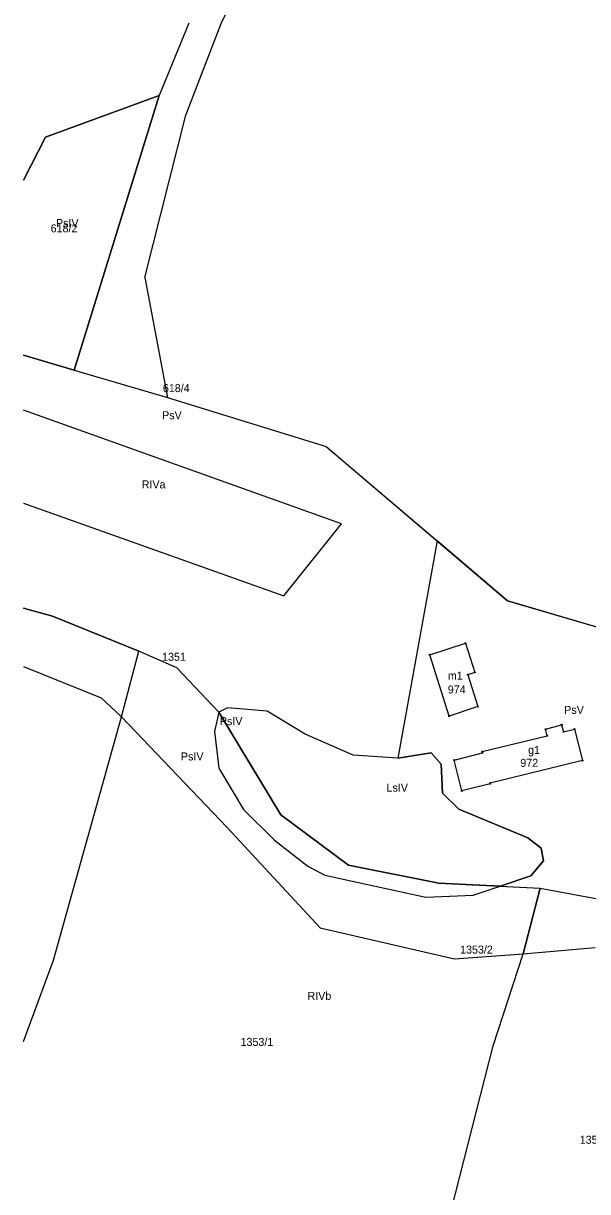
# Model space of a CAD drawing. Extents: x 7498273 to 7499989, y 5499795 to 5500810.
# Drawn here: x 7498273.2 to 7498378.9, y 5500193.5 to 5500412.5 of the extents above; entities that cross this region are included whole.
import ezdxf

# ---------------------------------------------------------------- set-up
doc = ezdxf.new("R2010")
doc.units = 0
for name, color, linetype in [('209-oznaczenie konturu klasyfikacyjnego', 7, 'Continuous'), ('211-numer działki ewidencyjnej', 7, 'Continuous'), ('217-kontur klasyfikacyjny', 7, 'Continuous'), ('218-kontur użytku gruntowego', 7, 'Continuous'), ('219-działka ewidencyjna', 7, 'Continuous'), ('312-budynek ewidencyjny', 7, 'Continuous'), ('312-oznaczenie budynku ewidencyjnego', 7, 'Continuous'), ('312-oznaczenie budynku ewidencyjnego-Atr117', 7, 'Continuous'), ('Punkt budynku', 7, 'Continuous')]:
    doc.layers.add(name, color=color, linetype=linetype)

# ---------------------------------------------------------------- blocks, each defined once
blk = doc.blocks.new('PUNKTBUD')
blk.add_circle((0, 0), 0.09)

msp = doc.modelspace()

# ---------------------------------------------------------------- linework, layer by layer
at = {"layer": '217-kontur klasyfikacyjny'}
for points in [[(7498304.21, 5500412.52), (7498298.63, 5500398.96)], [(7498298.63, 5500398.96), (7498277.31, 5500391.13)], [(7498298.63, 5500398.96), (7498282.7, 5500347.49)], [(7498277.31, 5500391.13), (7498273.174, 5500383.069)], [(7498282.7, 5500347.49), (7498273.174, 5500350.256)], [(7498282.7, 5500347.49), (7498300.17, 5500342.36)], [(7498300.17, 5500342.36), (7498329.95, 5500333.19)], [(7498332.78, 5500318.69), (7498273.174, 5500339.962)], [(7498329.95, 5500333.19), (7498350.74, 5500315.46)], [(7498273.174, 5500322.559), (7498322, 5500305.16)], [(7498322, 5500305.16), (7498332.78, 5500318.69)], [(7498350.74, 5500315.46), (7498343.36, 5500274.78)], [(7498363.93, 5500304.21), (7498350.74, 5500315.46)], [(7498381.55, 5500299.07), (7498363.93, 5500304.21)], [(7498278.63, 5500301.34), (7498273.174, 5500302.837)], [(7498294.84, 5500294.79), (7498278.63, 5500301.34)], [(7498301.93, 5500291.67), (7498294.84, 5500294.79)], [(7498273.174, 5500291.909), (7498287.76, 5500286.06)], [(7498309.84, 5500283.36), (7498301.93, 5500291.67)], [(7498287.76, 5500286.06), (7498291.54, 5500282.5)], [(7498311.42, 5500284.16), (7498309.84, 5500283.36)], [(7498318.87, 5500283.54), (7498311.42, 5500284.16)], [(7498325.97, 5500279.26), (7498318.87, 5500283.54)], [(7498291.54, 5500282.5), (7498311.35, 5500261.75)], [(7498309.84, 5500283.36), (7498309, 5500279.74)], [(7498321.44, 5500264.13), (7498309.84, 5500283.36)], [(7498309, 5500279.74), (7498309.83, 5500272.91)], [(7498335.01, 5500275.33), (7498325.97, 5500279.26)], [(7498343.36, 5500274.78), (7498335.01, 5500275.33)], [(7498349.61, 5500275.76), (7498343.36, 5500274.78)], [(7498351.51, 5500273.61), (7498349.61, 5500275.76)], [(7498309.83, 5500272.91), (7498314.45, 5500265.12)], [(7498351.73, 5500268.22), (7498351.51, 5500273.61)], [(7498354.79, 5500265.2), (7498351.73, 5500268.22)], [(7498314.45, 5500265.12), (7498320.24, 5500259.36)], [(7498334.13, 5500254.67), (7498321.44, 5500264.13)], [(7498367.76, 5500259.81), (7498354.79, 5500265.2)], [(7498311.35, 5500261.75), (7498328.84, 5500242.96)], [(7498320.24, 5500259.36), (7498326.47, 5500254.5)], [(7498370.26, 5500257.91), (7498367.76, 5500259.81)], [(7498370.65, 5500255.5), (7498370.26, 5500257.91)], [(7498368.28, 5500252.7), (7498370.65, 5500255.5)], [(7498326.47, 5500254.5), (7498329.66, 5500252.82)], [(7498329.66, 5500252.82), (7498348.63, 5500248.7)], [(7498351.07, 5500251.35), (7498334.13, 5500254.67)], [(7498362.54, 5500250.78), (7498351.07, 5500251.35)], [(7498357.46, 5500249.08), (7498362.54, 5500250.78)], [(7498362.54, 5500250.78), (7498368.28, 5500252.7)], [(7498362.54, 5500250.78), (7498370.04, 5500250.4)], [(7498348.63, 5500248.7), (7498357.46, 5500249.08)], [(7498370.04, 5500250.4), (7498366.87, 5500238.07)], [(7498370.04, 5500250.4), (7498379.48, 5500248.65)], [(7498328.84, 5500242.96), (7498354.02, 5500237.13)], [(7498354.02, 5500237.13), (7498366.87, 5500238.07)], [(7498366.87, 5500238.07), (7498380.36, 5500239.26)]]:
    msp.add_lwpolyline(points, dxfattribs=at)
at = {"layer": '218-kontur użytku gruntowego'}
for points in [[(7498304.21, 5500412.52), (7498298.63, 5500398.96)], [(7498298.63, 5500398.96), (7498277.31, 5500391.13)], [(7498298.63, 5500398.96), (7498282.7, 5500347.49)], [(7498277.31, 5500391.13), (7498273.174, 5500383.069)], [(7498273.174, 5500350.256), (7498282.7, 5500347.49)], [(7498282.7, 5500347.49), (7498300.17, 5500342.36)], [(7498300.17, 5500342.36), (7498329.95, 5500333.19)], [(7498332.78, 5500318.69), (7498273.174, 5500339.962)], [(7498329.95, 5500333.19), (7498350.74, 5500315.46)], [(7498273.174, 5500322.559), (7498322, 5500305.16)], [(7498322, 5500305.16), (7498332.78, 5500318.69)], [(7498350.74, 5500315.46), (7498343.36, 5500274.78)], [(7498363.93, 5500304.21), (7498350.74, 5500315.46)], [(7498381.55, 5500299.07), (7498363.93, 5500304.21)], [(7498278.63, 5500301.34), (7498273.174, 5500302.837)], [(7498294.84, 5500294.79), (7498278.63, 5500301.34)], [(7498301.93, 5500291.67), (7498294.84, 5500294.79)], [(7498273.174, 5500291.909), (7498287.76, 5500286.06)], [(7498309.84, 5500283.36), (7498301.93, 5500291.67)], [(7498287.76, 5500286.06), (7498291.54, 5500282.5)], [(7498311.42, 5500284.16), (7498309.84, 5500283.36)], [(7498318.87, 5500283.54), (7498311.42, 5500284.16)], [(7498325.97, 5500279.26), (7498318.87, 5500283.54)], [(7498291.54, 5500282.5), (7498311.35, 5500261.75)], [(7498309.84, 5500283.36), (7498309, 5500279.74)], [(7498309.84, 5500283.36), (7498321.44, 5500264.13)], [(7498309, 5500279.74), (7498309.83, 5500272.91)], [(7498335.01, 5500275.33), (7498325.97, 5500279.26)], [(7498343.36, 5500274.78), (7498335.01, 5500275.33)], [(7498343.36, 5500274.78), (7498349.61, 5500275.76)], [(7498349.61, 5500275.76), (7498351.51, 5500273.61)], [(7498309.83, 5500272.91), (7498314.45, 5500265.12)], [(7498351.51, 5500273.61), (7498351.73, 5500268.22)], [(7498351.73, 5500268.22), (7498354.79, 5500265.2)], [(7498314.45, 5500265.12), (7498320.24, 5500259.36)], [(7498321.44, 5500264.13), (7498334.13, 5500254.67)], [(7498354.79, 5500265.2), (7498367.76, 5500259.81)], [(7498311.35, 5500261.75), (7498328.84, 5500242.96)], [(7498320.24, 5500259.36), (7498326.47, 5500254.5)], [(7498367.76, 5500259.81), (7498370.26, 5500257.91)], [(7498370.26, 5500257.91), (7498370.65, 5500255.5)], [(7498370.65, 5500255.5), (7498368.28, 5500252.7)], [(7498326.47, 5500254.5), (7498329.66, 5500252.82)], [(7498329.66, 5500252.82), (7498348.63, 5500248.7)], [(7498334.13, 5500254.67), (7498351.07, 5500251.35)], [(7498351.07, 5500251.35), (7498362.54, 5500250.78)], [(7498357.46, 5500249.08), (7498362.54, 5500250.78)], [(7498368.28, 5500252.7), (7498362.54, 5500250.78)], [(7498362.54, 5500250.78), (7498370.04, 5500250.4)], [(7498348.63, 5500248.7), (7498357.46, 5500249.08)], [(7498370.04, 5500250.4), (7498366.87, 5500238.07)], [(7498370.04, 5500250.4), (7498379.48, 5500248.65)], [(7498328.84, 5500242.96), (7498354.02, 5500237.13)], [(7498354.02, 5500237.13), (7498366.87, 5500238.07)], [(7498366.87, 5500238.07), (7498380.36, 5500239.26)]]:
    msp.add_lwpolyline(points, dxfattribs=at)
at = {"layer": '219-działka ewidencyjna'}
for points in [[(7498310.27, 5500412.43), (7498332.23, 5500456.63)], [(7498304.21, 5500412.52), (7498298.63, 5500398.96)], [(7498304.21, 5500412.52), (7498298.63, 5500398.96)], [(7498303.6, 5500395.27), (7498310.27, 5500412.43)], [(7498277.31, 5500391.13), (7498298.63, 5500398.96)], [(7498277.31, 5500391.13), (7498298.63, 5500398.96)], [(7498282.7, 5500347.49), (7498298.63, 5500398.96)], [(7498295.94, 5500364.84), (7498303.6, 5500395.27)], [(7498273.174, 5500383.069), (7498277.31, 5500391.13)], [(7498273.174, 5500383.069), (7498277.31, 5500391.13)], [(7498295.94, 5500364.84), (7498300.17, 5500342.36)], [(7498282.7, 5500347.49), (7498273.174, 5500350.256)], [(7498282.7, 5500347.49), (7498300.17, 5500342.36)], [(7498300.17, 5500342.36), (7498329.95, 5500333.19)], [(7498329.95, 5500333.19), (7498363.93, 5500304.21)], [(7498363.93, 5500304.21), (7498408.16, 5500291.3)], [(7498273.174, 5500302.837), (7498278.63, 5500301.34)], [(7498278.63, 5500301.34), (7498294.84, 5500294.79)], [(7498291.54, 5500282.5), (7498294.84, 5500294.79)], [(7498301.93, 5500291.67), (7498294.84, 5500294.79)], [(7498273.174, 5500291.909), (7498287.76, 5500286.06)], [(7498301.93, 5500291.67), (7498309.84, 5500283.36)], [(7498287.76, 5500286.06), (7498291.54, 5500282.5)], [(7498278.81, 5500236.91), (7498291.54, 5500282.5)], [(7498291.54, 5500282.5), (7498311.35, 5500261.75)], [(7498309.84, 5500283.36), (7498321.44, 5500264.13)], [(7498321.44, 5500264.13), (7498334.13, 5500254.67)], [(7498311.35, 5500261.75), (7498328.84, 5500242.96)], [(7498334.13, 5500254.67), (7498351.07, 5500251.35)], [(7498351.07, 5500251.35), (7498370.04, 5500250.4)], [(7498366.87, 5500238.07), (7498370.04, 5500250.4)], [(7498370.04, 5500250.4), (7498409.43, 5500243.11)], [(7498328.84, 5500242.96), (7498354.02, 5500237.13)], [(7498354.02, 5500237.13), (7498366.87, 5500238.07)], [(7498361.22, 5500220.85), (7498366.87, 5500238.07)], [(7498273.174, 5500221.657), (7498278.81, 5500236.91)], [(7498345.48, 5500159.15), (7498361.22, 5500220.85)]]:
    msp.add_lwpolyline(points, dxfattribs=at)
at = {"layer": '312-budynek ewidencyjny'}
for points in [[(7498349.35, 5500294.15), (7498356.04, 5500296.28)], [(7498356.04, 5500296.28), (7498357.78, 5500290.82)], [(7498353.01, 5500282.65), (7498349.35, 5500294.15)], [(7498357.78, 5500290.82), (7498356.49, 5500290.39)], [(7498356.49, 5500290.39), (7498358.38, 5500284.41)], [(7498358.38, 5500284.41), (7498353.01, 5500282.65)], [(7498371.08, 5500280.18), (7498374.08, 5500281.01)], [(7498371.38, 5500278.96), (7498371.08, 5500280.18)], [(7498374.08, 5500281.01), (7498374.4, 5500279.7)], [(7498374.4, 5500279.7), (7498376.46, 5500280.2)], [(7498376.46, 5500280.2), (7498377.96, 5500274.3)], [(7498359.16, 5500275.98), (7498371.38, 5500278.96)], [(7498353.9, 5500274.39), (7498359.22, 5500275.75)], [(7498359.22, 5500275.75), (7498359.16, 5500275.98)], [(7498355.38, 5500268.61), (7498353.9, 5500274.39)], [(7498377.96, 5500274.3), (7498360.67, 5500270.08)], [(7498360.7, 5500269.95), (7498355.38, 5500268.61)], [(7498360.67, 5500270.08), (7498360.7, 5500269.95)]]:
    msp.add_lwpolyline(points, dxfattribs=at)

# ---------------------------------------------------------------- block references
at = {"layer": 'Punkt budynku'}
for p in [(7498356.04, 5500296.28), (7498349.35, 5500294.15), (7498356.49, 5500290.39), (7498357.78, 5500290.82), (7498358.38, 5500284.41), (7498353.01, 5500282.65), (7498371.08, 5500280.18), (7498371.38, 5500278.96), (7498374.08, 5500281.01), (7498374.4, 5500279.7), (7498376.46, 5500280.2), (7498359.16, 5500275.98), (7498359.22, 5500275.75), (7498353.9, 5500274.39), (7498377.96, 5500274.3), (7498355.38, 5500268.61), (7498360.67, 5500270.08), (7498360.7, 5500269.95)]:
    msp.add_blockref('PUNKTBUD', p, dxfattribs=at)

# ---------------------------------------------------------------- texts
at = {"layer": '209-oznaczenie konturu klasyfikacyjnego'}
for s, p in [('PsIV', (7498279.29, 5500374.3)), ('PsV', (7498299.18, 5500338.28)), ('RIVa', (7498295.36, 5500325.31)), ('PsV', (7498374.56, 5500283.06)), ('PsIV', (7498310, 5500280.95)), ('PsIV', (7498302.71, 5500274.33)), ('LsIV', (7498341.25, 5500268.47)), ('RIVb', (7498326.44, 5500229.46))]:
    msp.add_text(s, height=1.5, dxfattribs=at).set_placement(p)
at = {"layer": '211-numer działki ewidencyjnej'}
for s, p in [('618/2', (7498278.29, 5500373.3)), ('618/4', (7498299.33, 5500343.36)), ('1351', (7498299.18, 5500293)), ('1353/2', (7498355.04, 5500238.13)), ('1353/1', (7498313.89, 5500220.83)), ('1354/1', (7498377.46, 5500202.49))]:
    msp.add_text(s, height=1.5, dxfattribs=at).set_placement(p)
at = {"layer": '312-oznaczenie budynku ewidencyjnego'}
for s, p in [('974', (7498352.74, 5500286.88)), ('972', (7498366.33, 5500273.13))]:
    msp.add_text(s, height=1.5, dxfattribs=at).set_placement(p)
at = {"layer": '312-oznaczenie budynku ewidencyjnego-Atr117'}
for s, p in [('m1', (7498352.745, 5500289.47)), ('g1', (7498367.789, 5500275.55))]:
    msp.add_text(s, height=1.5, dxfattribs=at).set_placement(p)

doc.saveas('drawing.dxf')
